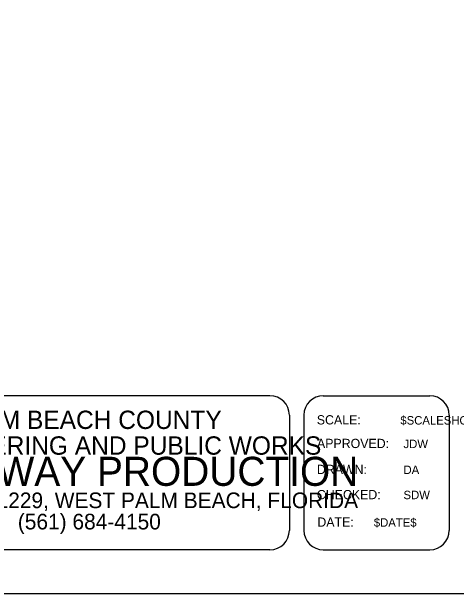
# Model space of a CAD drawing. Extents: x 783907 to 784590, y 832093 to 832609.
# Drawn here: x 784329.43 to 784349.68, y 832093.25 to 832119.75 of the extents above; entities that cross this region are included whole.
import ezdxf

# ---------------------------------------------------------------- set-up
doc = ezdxf.new("R2010")
doc.units = 0
for name, color, linetype in [('Default', 7, 'Continuous'), ('PlotBorder_dp', 7, 'Continuous'), ('TextMinor', 7, 'Continuous')]:
    doc.layers.add(name, color=color, linetype=linetype)

msp = doc.modelspace()

# ---------------------------------------------------------------- linework, layer by layer
at = {"layer": 'Default'}
for p, q in [((784341.196, 832102.255), (784316.937, 832102.255)), ((784343.622, 832102.255), (784348.474, 832102.255)), ((784342.078, 832101.373), (784342.078, 832096.123)), ((784342.74, 832101.373), (784342.74, 832096.123)), ((784349.356, 832101.373), (784349.356, 832096.123)), ((784341.196, 832095.241), (784316.937, 832095.241)), ((784343.622, 832095.241), (784348.474, 832095.241))]:
    msp.add_line(p, q, dxfattribs=at)
for centre, major_axis, start_param, end_param in [((784341.196, 832101.373), (0, 0.882), 4.712389, 6.283185), ((784343.622, 832101.373), (0, 0.882), 0, 1.570796), ((784348.474, 832101.373), (0, 0.882), 4.712389, 6.283185), ((784341.196, 832096.123), (0, 0.882), 3.141593, 4.712389), ((784343.622, 832096.123), (0, -0.882), 4.712389, 6.283185), ((784348.474, 832096.123), (0, -0.882), 0, 1.570796)]:
    msp.add_ellipse(centre, major_axis=major_axis, ratio=0.999927, start_param=start_param, end_param=end_param, dxfattribs=at)
at = {"layer": 'PlotBorder_dp'}
msp.add_lwpolyline([(784223.94, 832093.255), (784388.94, 832093.255), (784388.94, 832199.255), (784223.94, 832199.255)], close=True, dxfattribs=at)

# ---------------------------------------------------------------- texts
at = {"layer": 'Default'}
for s, height, p in [('PALM BEACH COUNTY', 0.83446, (784326.784, 832100.744)), ('SCALE:', 0.4207, (784343.328, 832100.95)), ('ENGINEERING AND PUBLIC WORKS', 0.83468, (784324.184, 832099.572)), ('APPROVED:', 0.4207, (784343.336, 832099.874)), ('JDW', 0.3855, (784347.275, 832099.871)), ('ROADWAY PRODUCTION', 1.32369, (784323.681, 832098.153)), ('DRAWN:', 0.4207, (784343.33, 832098.692)), ('DA ', 0.3855, (784347.275, 832098.69)), ('CHECKED:', 0.4207, (784343.329, 832097.544)), ('SDW', 0.3855, (784347.275, 832097.545)), ('P.O. BOX 21229, WEST PALM BEACH, FLORIDA', 0.71224, (784323.772, 832097.137)), ('(561) 684-4150', 0.71224, (784329.714, 832096.167)), ('DATE:', 0.4207, (784343.353, 832096.292)), ('$DATE$', 0.3855, (784345.924, 832096.29))]:
    msp.add_text(s, height=height, dxfattribs=at).set_placement(p)
at = {"layer": 'TextMinor'}
msp.add_text('$SCALESHORT$', height=0.38546, dxfattribs=at).set_placement((784347.131, 832100.944))

doc.saveas('drawing.dxf')
